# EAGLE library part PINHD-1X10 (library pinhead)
PIN HEADER
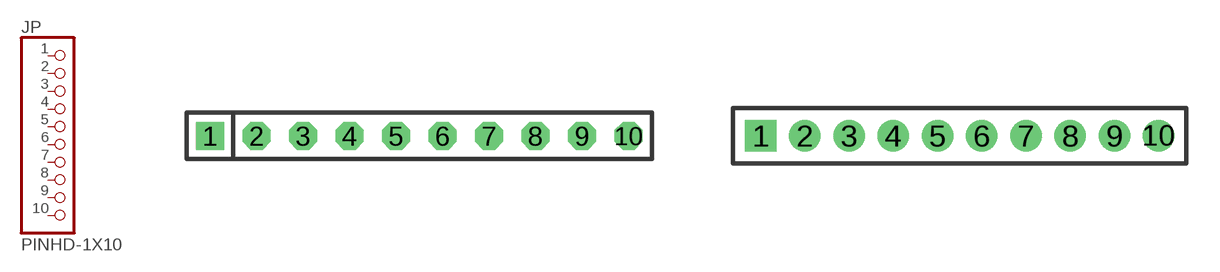
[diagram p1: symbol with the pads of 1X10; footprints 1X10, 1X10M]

Designator prefix JP

## PINHD-1X10  [1X10]
1  1  pas
2  2  pas
3  3  pas
4  4  pas
5  5  pas
6  6  pas
7  7  pas
8  8  pas
9  9  pas
10  10  pas

## PINHD-1X10M  [1X10M]
Pads as for 1X10

## Footprint 1X10 (pad centres in mm)
PIN HEADER - 0.1"
drill 1.016 square: 1 -11.43,0
drill 1.016 octagon: 2 -8.89,0; 3 -6.35,0; 4 -3.81,0; 5 -1.27,0; 6 1.27,0; 7 3.81,0; 8 6.35,0; 9 8.89,0; 10 11.43,0

## Footprint 1X10M (pad centres in mm)
PIN HEADER - 2MM"
drill 0.914 square: 1 -9,0
drill 0.914 round: 2 -7,0; 3 -5,0; 4 -3,0; 5 -1,0; 6 1,0; 7 3,0; 8 5,0; 9 7,0; 10 9,0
